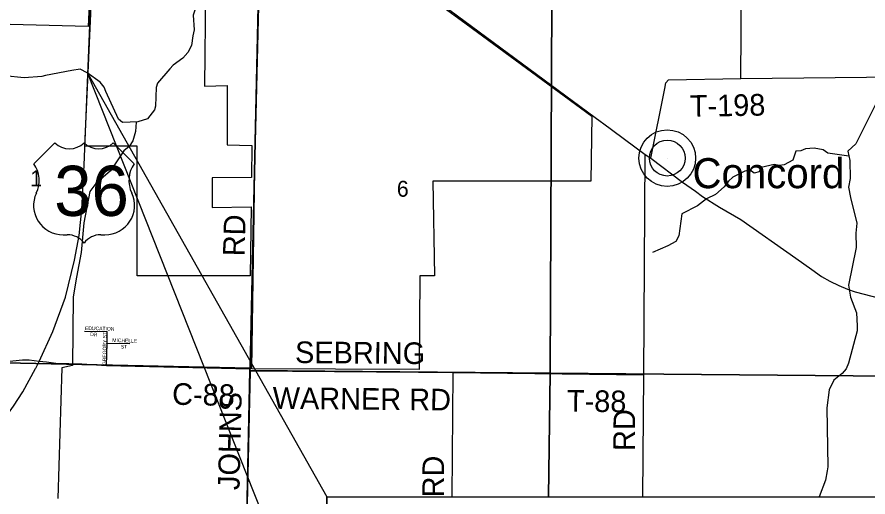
# Model space of a CAD drawing. Extents: x 0 to 1391, y -24 to 440.
# Drawn here: x 106.53 to 151.26, y 320.66 to 345.88 of the extents above; entities that cross this region are included whole.
import ezdxf

# ---------------------------------------------------------------- set-up
doc = ezdxf.new("R2010")
doc.units = 0
for name, color, linetype in [('GM_X_Corporation', 7, 'Continuous'), ('GM_X_County_Road', 7, 'Continuous'), ('GM_X_County_Road_Text', 7, 'Continuous'), ('GM_X_County_Subdivision', 7, 'Continuous'), ('GM_X_County_Subdivision_Text', 7, 'Continuous'), ('GM_X_Minor_River', 7, 'Continuous'), ('GM_X_Section', 7, 'Continuous'), ('GM_X_Section_Text', 7, 'Continuous'), ('GM_X_State_Route', 7, 'Continuous'), ('GM_X_Township_Road', 7, 'Continuous'), ('GM_X_Township_Road_Text', 7, 'Continuous'), ('GM_X_Unincorporated', 7, 'Continuous'), ('GM_X_Unincorporated_Location', 7, 'Continuous'), ('GM_X_Unincorporated_Text', 7, 'Continuous'), ('GM_X_US_Location', 7, 'Continuous'), ('GM_X_US_Route', 7, 'Continuous'), ('GM_X_US_Shield', 7, 'Continuous'), ('SH_Text', 7, 'Continuous')]:
    doc.layers.add(name, color=color, linetype=linetype)

msp = doc.modelspace()

# ---------------------------------------------------------------- linework, layer by layer
at = {"layer": 'GM_X_Corporation'}
for points in [[(110.426, 348.793), (110.272, 345.388), (105.479, 345.5)], [(116.434, 347.232), (116.391, 342.253), (117.585, 342.274), (117.586, 339.164), (118.873, 339.125), (118.857, 337.442), (116.787, 337.427), (116.787, 335.866), (118.842, 335.901), (118.785, 332.274), (112.858, 332.274), (112.858, 339.093), (110.097, 339.093), (110.535, 348.775)], [(128.993, 346.361), (130.142, 345.517), (136.752, 340.661), (136.693, 337.252), (128.391, 337.254), (128.478, 332.284), (127.701, 332.272), (127.679, 327.357), (118.877, 327.397), (119.037, 337.867), (119.071, 339.472), (119.26, 347.31)]]:
    msp.add_lwpolyline(points, dxfattribs=at)
at = {"layer": 'GM_X_County_Road'}
msp.add_lwpolyline([(118.786, 327.382), (111.239, 327.553), (109.944, 327.641), (108.575, 327.678), (108.082, 327.734), (107.705, 327.774), (107.166, 327.845), (106.828, 327.849), (105.812, 327.745), (105.291, 327.645), (103.738, 327.75), (103.99, 341.377)], dxfattribs=at)
at = {"layer": 'GM_X_County_Subdivision'}
for points in [[(110.081, 329.378), (111.28, 329.351)], [(111.266, 328.743), (111.266, 328.743), (111.28, 329.351)], [(111.239, 327.553), (111.266, 328.743)], [(111.266, 328.743), (112.466, 328.716)]]:
    msp.add_lwpolyline(points, dxfattribs=at)
at = {"layer": 'GM_X_Minor_River'}
for points in [[(119.007, 352.638), (118.743, 351.944), (118.473, 350.972), (118.384, 350.061), (118.271, 349.59), (118.302, 349.461), (118.257, 349.355), (118.196, 349.347), (117.348, 348.753), (116.932, 348.396), (116.683, 347.986), (116.676, 347.932), (116.639, 347.332), (116.322, 347.006), (116.042, 346.732), (115.793, 345.972), (115.841, 345.198), (115.781, 344.894), (115.714, 344.378), (115.51, 344.006), (115.253, 343.709), (114.738, 343.343), (114.567, 343.163)], [(110.214, 342.943), (109.848, 343.138), (109.409, 343.076), (108.037, 342.808), (107.833, 342.747), (106.915, 342.684), (105.884, 342.789)], [(114.567, 343.163), (113.919, 342.403), (113.846, 342.177), (113.805, 341.189), (113.763, 340.993), (113.397, 340.521), (112.891, 340.363), (112.084, 340.332), (111.874, 340.503), (111.208, 341.959), (111.113, 342.197), (110.913, 342.451), (110.214, 342.943)], [(151.898, 341.775), (150.624, 339.216), (150.206, 338.829), (150.311, 338.341), (150.331, 337.39), (150.239, 336.936), (150.343, 336.387), (150.683, 335.05), (150.627, 334.527), (150.651, 333.766), (150.248, 331.79), (150.351, 331.164), (150.662, 330.337), (150.703, 329.645), (150.698, 329.387), (150.247, 327.685), (150.112, 327.398), (149.902, 327.144), (149.469, 326.802), (149.223, 326.282), (149.098, 325.342), (149.146, 322.246), (149.119, 322.026), (149.034, 321.549), (148.701, 320.661)], [(112.793, 340.359), (112.762, 339.858), (112.615, 339.368), (112.422, 339.078), (112.155, 338.844), (111.44, 337.802), (110.685, 337.136), (110.358, 336.706), (110.041, 335.071), (109.91, 333.499), (109.659, 332.212), (109.482, 331.168)], [(150.263, 338.565), (149.153, 338.728), (148.906, 338.907), (148.435, 338.985), (147.985, 338.955), (147.732, 338.839), (147.473, 338.829), (147.319, 338.36), (146.858, 338.111), (146.598, 338.078), (146.34, 338.128), (145.652, 337.974), (145.541, 337.741), (145.281, 337.67), (145.079, 337.826), (144.796, 337.77), (144.158, 337.456), (143.933, 337.247), (143.699, 336.955), (143.243, 336.554), (142.782, 336.327), (142.31, 335.948), (141.48, 335.531), (141.314, 334.386), (141.171, 334.085), (140.74, 333.85), (139.942, 333.5)], [(109.482, 331.168), (109.459, 327.564), (108.894, 327.445), (108.686, 320.58)]]:
    msp.add_lwpolyline(points, dxfattribs=at)
at = {"layer": 'GM_X_Section'}
for points in [[(99.204, 347.93), (119.229, 347.252), (118.783, 327.433), (98.654, 327.856)], [(119.229, 347.252), (134.652, 346.763), (134.552, 327.163), (118.78, 327.297), (118.783, 327.433)], [(134.652, 346.763), (139.614, 346.725), (154.538, 346.603), (154.461, 326.988), (134.552, 327.163)], [(98.654, 327.856), (118.783, 327.433), (118.78, 327.297), (118.358, 307.167), (98.175, 307.59)]]:
    msp.add_lwpolyline(points, close=True, dxfattribs=at)
for points in [[(134.355, 311.225), (134.303, 306.969), (118.358, 307.167), (118.78, 327.297), (134.552, 327.163), (134.472, 320.661)], [(134.472, 320.661), (134.552, 327.163), (154.461, 326.988), (154.411, 320.661)]]:
    msp.add_lwpolyline(points, dxfattribs=at)
at = {"layer": 'GM_X_State_Route'}
for points in [[(128.422, 346.893), (128.747, 346.645), (129.695, 345.941), (137.258, 340.351)], [(137.258, 340.351), (137.311, 340.312), (139.555, 338.662)], [(139.555, 338.662), (139.849, 338.461), (141.519, 337.205), (142.19, 336.721), (142.574, 336.45), (143.462, 335.886), (144.577, 335.235), (147.468, 333.202), (148.306, 332.611), (148.827, 332.251), (149.255, 331.991), (149.725, 331.767), (150.179, 331.583), (150.596, 331.44), (154.427, 330.434)]]:
    msp.add_lwpolyline(points, dxfattribs=at)
at = {"layer": 'GM_X_Township_Road'}
msp.add_line((129.405, 320.661), (129.453, 327.176), dxfattribs=at)
for points in [[(144.58, 342.653), (144.735, 364.651)], [(119.071, 339.309), (119.071, 339.322), (119.258, 347.192)], [(139.849, 338.461), (140.583, 342.122), (140.637, 342.417), (140.786, 342.573), (144.58, 342.653), (154.5, 342.758)], [(119.037, 337.894), (119.071, 339.309)], [(139.435, 320.661), (139.481, 327.061), (139.555, 338.662)], [(118.786, 327.382), (119.037, 337.894)], [(118.354, 307.089), (118.813, 327.26)], [(118.813, 327.26), (118.799, 327.293), (118.786, 327.382)], [(127.646, 327.19), (118.813, 327.26)], [(139.481, 327.061), (129.453, 327.176), (127.646, 327.19)]]:
    msp.add_lwpolyline(points, dxfattribs=at)
at = {"layer": 'GM_X_Unincorporated'}
for radius in [1.488, 0.943]:
    msp.add_circle((140.715, 338.466), radius, dxfattribs=at)
at = {"layer": 'GM_X_Unincorporated_Location'}
msp.add_line((140.715, 338.466), (140.715, 338.466), dxfattribs=at)
at = {"layer": 'GM_X_US_Route'}
for points in [[(107.705, 327.774), (108.419, 329.346), (109.076, 331.156), (109.563, 333.102), (109.793, 334.399), (109.947, 335.757), (110.066, 338.096), (110.493, 348.491), (110.499, 348.652)], [(95.793, 313.615), (96.175, 314.01), (97.971, 315.957), (98.644, 316.686), (99.973, 318.124), (101.561, 319.86), (103.111, 321.521), (103.95, 322.426), (105.184, 323.798), (106.353, 325.428), (106.835, 326.191), (107.514, 327.4), (107.523, 327.418)], [(107.523, 327.418), (107.705, 327.774)]]:
    msp.add_lwpolyline(points, dxfattribs=at)
at = {"layer": 'GM_X_US_Shield'}
for p, q in [((108.52, 339.271), (107.421, 338.172)), ((112.695, 338.172), (111.596, 339.271)), ((108.959, 334.437), (109.179, 334.437)), ((110.937, 334.437), (111.157, 334.437))]:
    msp.add_line(p, q, dxfattribs=at)
for centre, radius, start, end in [((109.289, 340.056), 1.099, 225.573, 314.427), ((110.827, 340.056), 1.099, 225.573, 314.427), ((106.161, 337.29), 1.538, 334.5471, 35.0009), ((113.955, 337.29), 1.538, 144.9991, 205.4529), ((108.942, 335.975), 1.538, 154.8319, 270.6383), ((111.174, 335.975), 1.538, 269.3617, 25.1681), ((109.179, 333.338), 1.099, 36.8699, 90), ((110.937, 333.338), 1.099, 90, 143.1301)]:
    msp.add_arc(centre, radius, start, end, dxfattribs=at)
at = {"layer": 'SH_Text'}
for points in [[(110.264, 342.916), (122.817, 320.661), (122.817, 311.225)], [(122.817, 320.661), (173.716, 320.661), (173.716, 311.225), (122.817, 311.225)]]:
    msp.add_lwpolyline(points, close=True, dxfattribs=at)

# ---------------------------------------------------------------- texts
at = {"layer": 'GM_X_County_Road_Text'}
msp.add_text('C-88', height=1.1364, rotation=358.6274, dxfattribs=at).set_placement((114.677, 325.51))
at = {"layer": 'GM_X_County_Subdivision_Text'}
for s, rotation, p in [('EDUCATION', 358.5837, (110.109, 329.436)), ('DR', 356.9774, (110.376, 329.114)), ('GREGORY ST', 89.3329, (111.222, 327.584)), ('MICHELLE', 358.3643, (111.542, 328.803)), ('ST', 0, (111.991, 328.46))]:
    msp.add_text(s, height=0.1894, rotation=rotation, dxfattribs=at).set_placement(p)
at = {"layer": 'GM_X_Section_Text'}
for s, p in [('1', (107.225, 336.985)), ('6', (126.5, 336.435))]:
    msp.add_text(s, height=0.837, rotation=0, dxfattribs=at).set_placement(p)
at = {"layer": 'GM_X_Township_Road_Text'}
for s, rotation, p in [('T-198', 1.1116, (141.911, 340.628)), ('RD', 88.5189, (118.495, 333.295)), ('SEBRING', 359.5188, (121.145, 327.697)), ('JOHNS', 88.6728, (118.228, 321.011)), ('WARNER RD', 359.425, (119.97, 325.293)), ('T-88', 359.2931, (135.434, 325.145)), ('RD', 89.5054, (139.011, 323.071)), ('RD', 90, (128.982, 320.634))]:
    msp.add_text(s, height=1.1364, rotation=rotation, dxfattribs=at).set_placement(p)
at = {"layer": 'GM_X_Unincorporated_Text'}
msp.add_text('Concord', height=1.5795, rotation=0, dxfattribs=at).set_placement((142.041, 336.883))
at = {"layer": 'GM_X_US_Location'}
for s in ['0', '/']:
    msp.add_text(s, height=0.00379, dxfattribs=at).set_placement((110.057, 336.723))
msp.add_text('36', height=0.00379, rotation=0, dxfattribs=at).set_placement((109.275, 335.939))
at = {"layer": 'GM_X_US_Shield'}
msp.add_text('36', height=2.6367, dxfattribs=at).set_placement((108.491, 335.426))

doc.saveas('drawing.dxf')
